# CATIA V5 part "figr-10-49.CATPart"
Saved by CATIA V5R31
Part number: Part1
Bounding box of the stored display mesh (mm): x -75 to 75, y 0 to 282.665, z -39.154 to 114.529
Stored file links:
  D:\PROJECTS\Project 2021\US EDITION\CATIA V5 6R 2021\Resources\Part Files\c10_catia_v5_6r2021_prt\c10_catia_v5_6r2021_prt\figr-10-49.CATPart
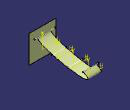
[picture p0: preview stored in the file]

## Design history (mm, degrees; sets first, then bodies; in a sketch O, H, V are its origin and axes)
Body1 (main body)
  Plane1: type Offset, RefPlane zx-plane, Offset 85
  Sketch1 on yz-plane, origin (0, 0, 0), H (0, 1, 0), V (0, 0, 1)
    line L1 (0, 114.5286) -> (0, -39.1536)
    point P1 (0, 114.5286)
    coincidence: P1 V
    vertical: L1 V
  Extrude1: Element1 Sketch1, Lim1 75, Lim2 75
  Plane2: type Offset, RefPlane Plane1, Offset 85
  Plane3: type Offset, RefPlane Plane2, Offset 85
  Sketch2 on zx-plane, origin (0, 0, 0), H (-1, 0, 0), V (0, 0, 1)
    line L1 (-43.9118, 70.4151) -> (71.5537, 70.4151)
    horizontal: L1 H
  Sketch3 on Plane1, origin (0, 85, 0), H (-1, 0, 0), V (0, 0, 1)
    line L1 (-29.1778, 30.4555) -> (46.4999, 30.4555)
    horizontal: L1 H
  Sketch4 on Plane2, origin (0, 170, 0), H (-1, 0, 0), V (0, 0, 1)
    line L1 (-27.284, 11.606) -> (54.5029, 11.606)
    horizontal: L1 H
  Sketch5 on Plane3, origin (0, 255, 0), H (-1, 0, 0), V (0, 0, 1)
    line L1 (-28.2106, 33.1442) -> (56.8447, 33.1442)
    horizontal: L1 H
  Sweep1: type Conic, Guide ({sweepconicextendedguide Guide Sketch2, Reference zx-plane, Angle 0}; Sketch3; Sketch4; Sketch5)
